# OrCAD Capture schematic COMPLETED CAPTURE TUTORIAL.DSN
size A; title: Transceiver; rev: A; company: EMA Design Automation; note: EMA-1; note: 225 Tech Park Drive; note: Rochester, NY 14623
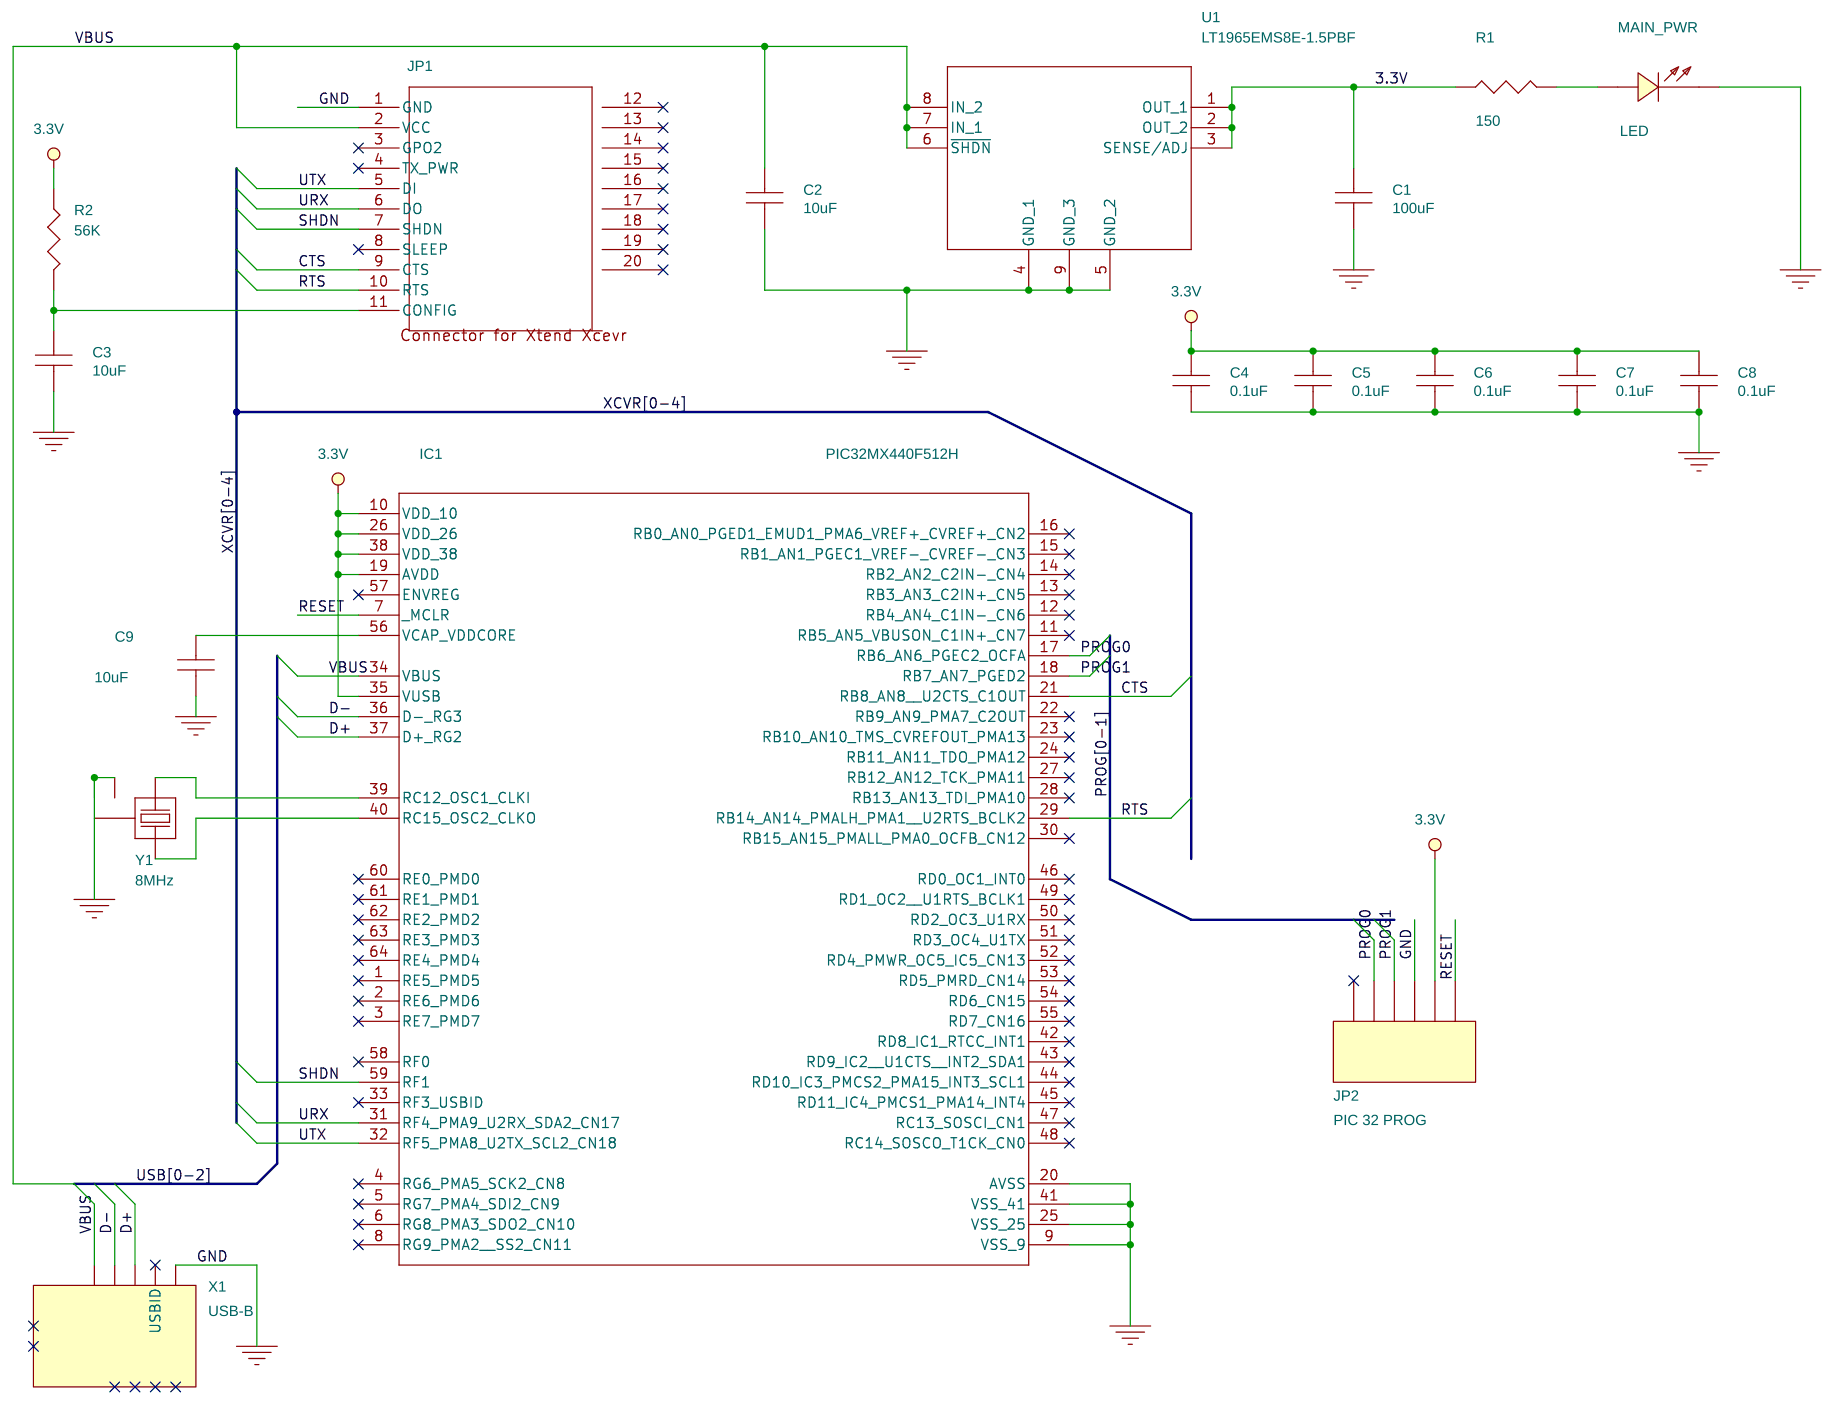
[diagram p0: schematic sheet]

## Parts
C1  100uF  [1210]
C2  10uF  [0402-cap]
C3  10uF  [0402-cap]
C4  0.1uF  [0402-cap]
C5  0.1uF  [0402-cap]
C6  0.1uF  [0402-cap]
C7  0.1uF  [0402-cap]
C8  0.1uF  [0402-cap]
C9  10uF  [0402-cap]
IC1  PIC32MX440F512H  [sqfp-s-10x10-64]
JP1  XTEND-DIGI-MODEM  [xtend-digi-modem]
JP2  PIC 32 PROG  [1x06_lock]
MAIN_PWR  LED  [LED_LNJ]
R1  150  [0402-res]
R2  56K  [0402-res]
U1  LT1965EMS8E-1.5PBF  [SOP65P490X110-9N]
X1  USB-B  [USB-MICROB]
Y1  8MHz  [crystal-smd]

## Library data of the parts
C1 = CAP_NP: Manufacturer_Name: Murata; Manufacturer_Part_Number: GRM32EC80J107ME20L; Part Number: 490-6533-1-ND; Vendor: Digi-Key
C2 C3 C9 = CAP_NP: Manufacturer_Name: Murata; Manufacturer_Part_Number: GRJ155R60J106ME11D; Part Number: 490-13211-2-ND; Vendor: Digi-Key
C4-C8 = CAP_NP: Manufacturer_Name: Samsung; Manufacturer_Part_Number: CL05F104ZO5NNNC; Part Number: 1276-1004-1-ND; Vendor: Digi-Key
IC1 = PIC32MX440F512H: Manufacturer_Name: Microchip; Manufacturer_Part_Number: PIC32MX440F512H-MXR; Part Number: PIC32MX440F512H-MXR; Vendor: Digi-Key
JP1 = XTEND-DIGI-MODEM: Vendor: Digi-Key
JP2 = M06_LOCK: Manufacturer_Name: TE Connectivity; Manufacturer_Part_Number: 640456-6; Part Number: A1923-ND; Vendor: Digi-Key
MAIN_PWR = LED: Manufacturer_Name: LITE-ON, INC; Manufacturer_Part_Number: LTST-C191KRKT; Part Number: 160-1447-2-ND; Vendor: Digi-Key
R1 = RESISTOR: Manufacturer_Name: Samsung; Manufacturer_Part_Number: RCS1005F151CS; Part Number: RCS1005F151CS-ND; Vendor: Digi-Key
R2 = RESISTOR: Manufacturer_Name: Panasonic; Manufacturer_Part_Number: ERA-2AEB563X; Part Number: P56KDCCT-ND; Vendor: Digi-Key
U1 = LT1965EMS8E-1_0.5PBF: 3D_Image_URL: https://componentsearchengine.com/2D/0T/583674.2.1.png; Body_Length: 3.102; Body_Width: 3.102; Category: Integrated Circuit; Confidence: C3 - Community checked; Height: 1.1; Package_Category: Small Outline Packages; Part Number: LT1965EMS8E-1.5#PBF-ND; Pin_Count: 9; Released_Date: 2017-01-11 17:02:35; Source_Version: 2.1; Status: Released; Vendor: Digi-Key; cdn_id: {"manufacturer":"Linear Technology","manufacturerPartNumber":"LT1965EMS8E-1.5PBF"}
X1 = USB-MICROB: Manufacturer_Name: Amphenol; Manufacturer_Part_Number: 10104110-0001LF; Part Number: 609-4052-ND; Vendor: Digi-Key
Y1 = CRYSTAL: Manufacturer_Name: Abracon; Manufacturer_Part_Number: ABM3-8MHZ-CL-R500-B1G; Part Number: ABM3-8MHZ-CL-R500-B1G; Vendor: Digi-Key

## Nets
3.3V: C1.1 C4.1 C5.1 C6.1 C7.1 C8.1 IC1.10(VDD) IC1.19(AVDD) IC1.26(VDD) IC1.35(VUSB) IC1.38(VDD) JP2.2 R1.1 R2.1 U1.1(OUT) U1.2(OUT) U1.3(SENSE/ADJ)
GND: C1.2 C2.2 C3.2 C4.2 C5.2 C6.2 C7.2 C8.2 C9.2 IC1.9(VSS) IC1.20(AVSS) IC1.25(VSS) IC1.41(VSS) JP1.1(GND) JP2.3 MAIN_PWR.1(CATHODE) U1.4(GND_1) U1.5(GND_2) U1.9(GND_3) X1.GND Y1.2(GND) Y1.4(GND)
VBUS: C2.1 IC1.34(VBUS) JP1.2(VCC) U1.6(~{SHDN}) U1.7(IN_1) U1.8(IN_2) X1.VBUS
CTS: IC1.21(RB8_AN8__U2CTS_C1OUT) JP1.9(CTS)
D+: IC1.37(D+_RG2) X1.D+
D-: IC1.36(D-_RG3) X1.D-
PROG0: IC1.17(RB6_AN6_PGEC2_OCFA) JP2.5
PROG1: IC1.18(RB7_AN7_PGED2) JP2.4
RESET: IC1.7(_MCLR) JP2.1
RTS: IC1.29(RB14_AN14_PMALH_PMA1__U2RTS_BCLK2) JP1.10(RTS)
SHDN: IC1.59(RF1) JP1.7(SHDN)
URX: IC1.31(RF4_PMA9_U2RX_SDA2_CN17) JP1.6(DO)
UTX: IC1.32(RF5_PMA8_U2TX_SCL2_CN18) JP1.5(DI)
N05718: C3.1 JP1.11(CONFIG) R2.2
N05832: MAIN_PWR.2(ANODE) R1.2
N05985: IC1.39(RC12_OSC1_CLKI) Y1.1
N05997: IC1.40(RC15_OSC2_CLKO) Y1.3
N06072: C9.1 IC1.56(VCAP_VDDCORE)

Not connected (* = marked no-connect by the designer): IC1 1(RE5_PMD5)* 2(RE6_PMD6)* 3(RE7_PMD7)* 4(RG6_PMA5_SCK2_CN8)* 5(RG7_PMA4_SDI2_CN9)* 6(RG8_PMA3_SDO2_CN10)* 8(RG9_PMA2__SS2_CN11)* 11(RB5_AN5_VBUSON_C1IN+_CN7)* 12(RB4_AN4_C1IN-_CN6)* 13(RB3_AN3_C2IN+_CN5)* 14(RB2_AN2_C2IN-_CN4)* 15(RB1_AN1_PGEC1_VREF-_CVREF-_CN3)* 16(RB0_AN0_PGED1_EMUD1_PMA6_VREF+_CVREF+_CN2)* 22(RB9_AN9_PMA7_C2OUT)* 23(RB10_AN10_TMS_CVREFOUT_PMA13)* 24(RB11_AN11_TDO_PMA12)* 27(RB12_AN12_TCK_PMA11)* 28(RB13_AN13_TDI_PMA10)* 30(RB15_AN15_PMALL_PMA0_OCFB_CN12)* 33(RF3_USBID)* 42(RD8_IC1_RTCC_INT1)* 43(RD9_IC2__U1CTS__INT2_SDA1)* 44(RD10_IC3_PMCS2_PMA15_INT3_SCL1)* 45(RD11_IC4_PMCS1_PMA14_INT4)* 46(RD0_OC1_INT0)* 47(RC13_SOSCI_CN1)* 48(RC14_SOSCO_T1CK_CN0)* 49(RD1_OC2__U1RTS_BCLK1)* 50(RD2_OC3_U1RX)* 51(RD3_OC4_U1TX)* 52(RD4_PMWR_OC5_IC5_CN13)* 53(RD5_PMRD_CN14)* 54(RD6_CN15)* 55(RD7_CN16)* 57(ENVREG)* 58(RF0)* 60(RE0_PMD0)* 61(RE1_PMD1)* 62(RE2_PMD2)* 63(RE3_PMD3)* 64(RE4_PMD4)*; JP1 3(GPO2)* 4(TX_PWR)* 8(SLEEP)* 12* 13* 14* 15* 16* 17* 18* 19* 20*; JP2 6*; X1 ID(USBID)* MT1* MT2* MT3* MT4* P_1* P_2*
